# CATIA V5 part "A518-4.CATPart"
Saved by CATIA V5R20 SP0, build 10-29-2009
Part number: A518-4
Source: Unknown
Property "ARTICLENO": "A518-4"
Property "BOMINFO": "A518-4"
Property "CODE": "A518-4"
Property "D": "63.000"
Property "H": "51.000"
Property "H1": "86.000"
Property "L": "80.000"
Property "L1": "60.000"
Property "LINA": "A518-4"
Property "NB": "A518-4"
Property "NBSYN": "$CODE."
Property "NN": "A518"
Property "NT": "Shock Absorber for Pad Retainer Pins"
Property "PINDIA": "63.000"
Property "R": "35.000"
Property "SUPPLIER": "CF"
Bounding box of the stored display mesh (mm): x -31.5 to 25.115, y 0 to 80, z -31.496 to 31.496
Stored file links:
  C:\Users\Utente\Desktop\3D files A518\A518-4.CATPart
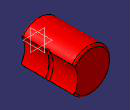
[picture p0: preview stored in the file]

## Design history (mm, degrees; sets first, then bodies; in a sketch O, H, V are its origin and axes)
Body1 "Geometry.1" (main body)
  Solid1 "A518-4.catpart": solid without history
